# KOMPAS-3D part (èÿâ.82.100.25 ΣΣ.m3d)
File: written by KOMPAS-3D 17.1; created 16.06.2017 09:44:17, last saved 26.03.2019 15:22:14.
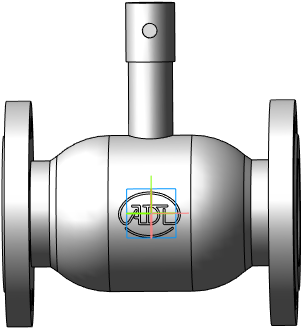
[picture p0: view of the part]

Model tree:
1. Операция без истории:2  (labels: Сталь 20  ГОСТ 1050-88)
